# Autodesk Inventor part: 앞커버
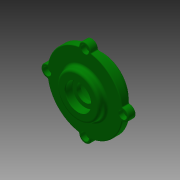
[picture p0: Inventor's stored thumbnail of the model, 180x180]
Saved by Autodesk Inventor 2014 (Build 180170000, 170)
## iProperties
Created: 2016-05
Part Number: 앞커버
Document SubType Name: Modeling
Designer: mduedu
Density: 2.71 g/cm^3
Material: 알루미늄 6061
Appearance: 진녹색
Author: mduedu
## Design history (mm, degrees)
sketch "스케치1"
  geometry: C1 r 32 at (0, 0); C2 r 44 at (0, 0); 1 further point
  constraints: 2 centre point, 2 coincident
  dimensions: "d33" = 88 diameter of C2; "d34" = 64 diameter of C1
extrude "돌출1" new body sketch "스케치1" distance "d0" = 8; taper "d1" = 0 deg
extrude "돌출2" join sketch "스케치1" distance "d2" = 8; taper "d3" = 0 deg; dims "d35" = 12, "d36" = 0
sketch "스케치6"
  geometry: C1 r 25 at (0, 0); 2 further points
  constraints: 2 coincident, 1 centre point
  dimensions: "d42" = 50 diameter of C1
extrude "돌출4" join sketch "스케치6" distance "d43" = 8; taper "d44" = 0 deg
sketch "스케치9"
  geometry: C1 r 7 at (0, 44); 2 further points
  constraints: 2 vertical alignment, 1 centre point, 1 other
  dimensions: "d70" = 14 diameter of C1
extrude "돌출5" join sketch "스케치9" stored distance "d71" = 10; taper "d72" = 0 deg
fillet "모깎기9" dims "d76" = 1
sketch "스케치10"
  geometry: C1 r 25 at (0, 0) reference; A1 r 1 centre (-44.284, 7.995) between (-44.249, 6.996) and (-43.3, 7.817) reference; A2 r 7 centre (-44, 0) between (-44.249, 6.996) and (-44.249, -6.996) reference; A3 r 1 centre (-44.284, -7.995) between (-43.3, -7.817) and (-44.249, -6.996) reference; A4 r 44 centre (0, 0) between (-43.3, -7.817) and (-7.817, -43.3) reference; A5 r 1 centre (-7.995, -44.284) between (-6.996, -44.249) and (-7.817, -43.3) reference; A6 r 7 centre (0, -44) between (-6.996, -44.249) and (6.996, -44.249) reference; A7 r 1 centre (7.995, -44.284) between (7.817, -43.3) and (6.996, -44.249) reference; A8 r 1 centre (7.995, 44.284) between (6.996, 44.249) and (7.817, 43.3) reference; A9 r 7 centre (0, 44) between (6.996, 44.249) and (-6.996, 44.249) reference; A10 r 1 centre (-7.995, 44.284) between (-7.817, 43.3) and (-6.996, 44.249) reference; A11 r 7 centre (44, 0) between (44.249, -6.996) and (44.249, 6.996) reference; A12 r 44 centre (0, 0) between (-7.817, 43.3) and (-43.3, 7.817) reference; A13 r 44 centre (0, 0) between (7.817, -43.3) and (43.3, -7.817) reference; A14 r 1 centre (44.284, -7.995) between (44.249, -6.996) and (43.3, -7.817) reference; A15 r 1 centre (44.284, 7.995) between (43.3, 7.817) and (44.249, 6.996) reference; A16 r 44 centre (0, 0) between (43.3, 7.817) and (7.817, 43.3) reference; 4 further points
  constraints: 3 coincident
hole "구멍3" sketch "스케치10" at (0, 44), (-44, 0), (0, -44), (44, 0) diameter "d77" = 5.5; stored, may be unused: countersink angle "d81" = 90 deg, drill point angle "d83" = 118 deg; dims "d78" = 6, "d79" = 9.5, "d80" = 5.4, "d82" = 8
fillet "모깎기10" dims "d84" = 1
fillet "모깎기7" dims "d68" = 3
fillet "모깎기8" dims "d69" = 3
sketch "스케치4"
  geometry: L1 (0, -12)-(0, 16); L2 (-20, -12)-(-20, 0); L3 (-20, 0)-(-15, 0); L4 (-15, 0)-(-15, 3); L5 (-15, 3)-(-10, 3); L6 (-10, 3)-(-10, 7.7); L7 (-10, 7.7)-(-15, 7.7); L8 (-15, 7.7)-(-15, 16); L9 (32, -12)-(-32, -12) reference; L10 (25, 16)-(-25, 16) reference; 1 further point
  constraints: 16 end point, 6 parallel, 3 point on line, 2 midpoint, 1 perpendicular, 1 vertical
  dimensions: "d15" = 40 diameter of L2 L1; "d16" = 30 diameter of L8 L1; "d18" = 12 distance of L2.start L2.end; "d19" = 3 distance of L3.end L4.end; "d20" = 30 diameter of L4 L1; "d21" = 20 diameter of L6 L1; "d45" = 8.3 distance of L7.end L8.end
revolve "회전1" sketch "스케치4" stored, may be unused: angle "d22" = 90 deg
fillet "모깎기2" dims "d23" = 3
fillet "모깎기3" dims "d24" = 0.3
chamfer "모따기2" distance "d46" = 1; stored, may be unused: second distance "d47" = 2, angle "d48" = 45 deg
chamfer "모따기3" distance "d64" = 0.8; stored, may be unused: second distance "d65" = 2, angle "d66" = 30 deg
node "솔리드1"
pattern_circular "원형 패턴1" dims angle "d74" = 360 deg
node "투영된 루프1"
